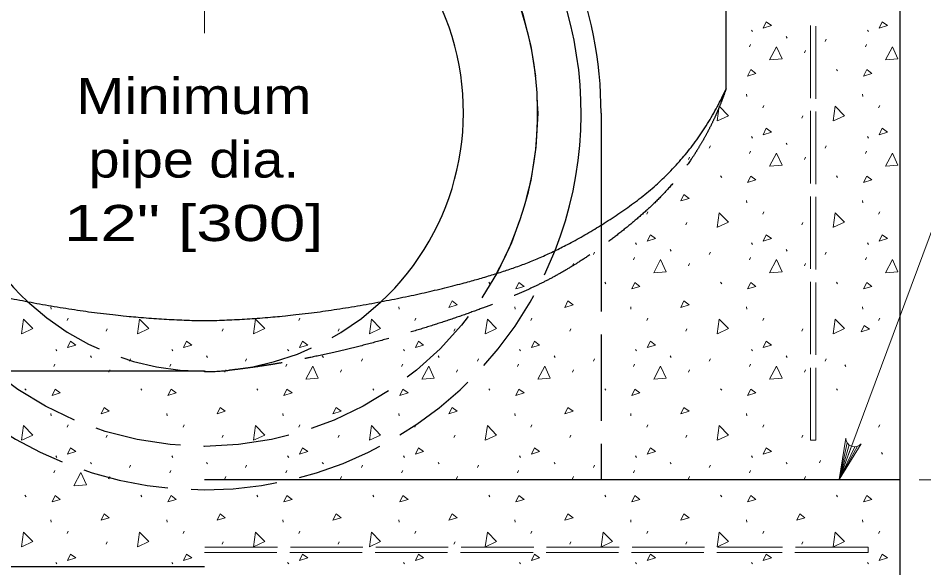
# Model space of a CAD drawing. Extents: x 1083.1 to 1117.1, y 719.4 to 763.4.
# Drawn here: x 1093.643 to 1097.549, y 728.741 to 731.113 of the extents above; entities that cross this region are included whole.
import ezdxf
from ezdxf.enums import TextEntityAlignment as Align

# ---------------------------------------------------------------- set-up
doc = ezdxf.new("R2010")
doc.units = 0
doc.header["$LTSCALE"] = 0.062
doc.linetypes.add('DOT_DASHED', pattern=[7.7, 5, -1.2, 0.3, -1.2])
doc.linetypes.add('LONG_DASHED', pattern=[7.5, 6, -1.5])
doc.layers.add('1', color=7, linetype='Continuous', lineweight=13)

msp = doc.modelspace()

# ---------------------------------------------------------------- linework, layer by layer
at = {"layer": '1', "lineweight": 25}
for p, q in [((1096.69608, 730.80725), (1096.69608, 733.88517)), ((1096.15717, 730.70242), (1096.15717, 730.21942)), ((1094.44633, 729.58892), (1091.19642, 729.58892)), ((1094.03408, 729.12525), (1094.0385, 729.13525)), ((1097.44608, 729.12017), (1094.44633, 729.12017)), ((1094.44633, 728.74525), (1091.19642, 728.74525))]:
    msp.add_line(p, q, dxfattribs=at)
at = {"layer": '1', "linetype": 'DOT_DASHED'}
msp.add_line((1094.44633, 731.04717), (1094.44633, 733.19283), dxfattribs=at)
at = {"layer": '1', "linetype": 'LONG_DASHED'}
for p, q in [((1097.05975, 730.76783), (1097.05975, 731.08033)), ((1097.08258, 730.76508), (1097.08258, 731.07758)), ((1097.05975, 730.39958), (1097.05975, 730.712)), ((1097.08258, 730.39683), (1097.08258, 730.70933)), ((1097.05975, 730.03133), (1097.05975, 730.34375)), ((1097.08258, 730.02858), (1097.08258, 730.341)), ((1097.05975, 729.663), (1097.05975, 729.9755)), ((1097.08258, 729.66025), (1097.08258, 729.97275)), ((1097.05967, 729.29208), (1097.05967, 729.60458)), ((1097.08258, 729.292), (1097.08258, 729.6045)), ((1097.05967, 729.29208), (1097.08258, 729.292)), ((1094.44633, 728.80775), (1094.75875, 728.80775)), ((1094.44908, 728.83058), (1094.7615, 728.83058)), ((1094.81458, 728.80775), (1095.12708, 728.80775)), ((1094.81733, 728.83058), (1095.12983, 728.83058)), ((1095.18292, 728.80775), (1095.49542, 728.80775)), ((1095.18567, 728.83058), (1095.49817, 728.83058)), ((1095.55125, 728.80775), (1095.86375, 728.80775)), ((1095.554, 728.83058), (1095.8665, 728.83058)), ((1095.91958, 728.80775), (1096.23208, 728.80775)), ((1095.92233, 728.83058), (1096.23483, 728.83058)), ((1096.28783, 728.80775), (1096.60033, 728.80775)), ((1096.29058, 728.83058), (1096.60308, 728.83058)), ((1096.65617, 728.80775), (1096.69617, 728.80775)), ((1096.65892, 728.83058), (1096.69617, 728.83058)), ((1096.69617, 728.83058), (1096.94008, 728.83058)), ((1096.69617, 728.80775), (1096.93733, 728.80775)), ((1096.99317, 728.80775), (1097.30842, 728.80775)), ((1096.99592, 728.83058), (1097.30842, 728.83058)), ((1097.30842, 728.83058), (1097.30842, 728.80775))]:
    msp.add_line(p, q, dxfattribs=at)
at = {"layer": '1'}
for p, q in [((1096.80533, 731.06133), (1096.80983, 731.05467)), ((1096.95492, 731.03308), (1096.95933, 731.0265)), ((1097.30533, 731.06133), (1097.30983, 731.05467)), ((1096.797, 730.98817), (1096.80142, 730.99817)), ((1097.12383, 731.01142), (1097.12825, 731.02142)), ((1097.297, 730.98817), (1097.30142, 730.99817)), ((1097.03392, 730.96267), (1097.03833, 730.97267)), ((1097.17267, 730.89167), (1097.17708, 730.885)), ((1096.78483, 730.78517), (1096.786, 730.77517)), ((1097.28483, 730.78517), (1097.286, 730.77517)), ((1096.85408, 730.72625), (1096.8585, 730.73625)), ((1097.35408, 730.72625), (1097.3585, 730.73625)), ((1097.02275, 730.68083), (1097.02725, 730.69083)), ((1096.80533, 730.60208), (1096.80983, 730.59542)), ((1097.30533, 730.60208), (1097.30983, 730.59542)), ((1096.62383, 730.55208), (1096.62825, 730.56208)), ((1096.95492, 730.57375), (1096.95933, 730.56717)), ((1097.12383, 730.55208), (1097.12825, 730.56208)), ((1096.797, 730.52892), (1096.80142, 730.53892)), ((1097.297, 730.52892), (1097.30142, 730.53892)), ((1096.53392, 730.50333), (1096.53833, 730.51333)), ((1097.03392, 730.50333), (1097.03833, 730.51333)), ((1096.67267, 730.43233), (1096.67708, 730.42567)), ((1097.17267, 730.43233), (1097.17708, 730.42567)), ((1096.78483, 730.32583), (1096.786, 730.31583)), ((1097.28483, 730.32583), (1097.286, 730.31583)), ((1096.35408, 730.26692), (1096.3585, 730.27692)), ((1096.85408, 730.26692), (1096.8585, 730.27692)), ((1097.35408, 730.26692), (1097.3585, 730.27692)), ((1096.15792, 730.20992), (1096.15942, 730.22083)), ((1096.52275, 730.22142), (1096.52725, 730.23142)), ((1097.02275, 730.22142), (1097.02725, 730.23142)), ((1096.30533, 730.14275), (1096.30983, 730.13608)), ((1096.80533, 730.14275), (1096.80983, 730.13608)), ((1097.30533, 730.14275), (1097.30983, 730.13608)), ((1095.95925, 730.10817), (1095.95942, 730.10783)), ((1096.12392, 730.09275), (1096.12833, 730.10275)), ((1096.45492, 730.1145), (1096.45933, 730.10783)), ((1096.62383, 730.09275), (1096.62825, 730.10275)), ((1096.95492, 730.1145), (1096.95933, 730.10783)), ((1097.12383, 730.09275), (1097.12825, 730.10275)), ((1096.034, 730.044), (1096.03842, 730.054)), ((1096.297, 730.06958), (1096.30142, 730.07958)), ((1096.53392, 730.044), (1096.53833, 730.054)), ((1096.797, 730.06958), (1096.80142, 730.07958)), ((1097.03392, 730.044), (1097.03833, 730.054)), ((1097.297, 730.06958), (1097.30142, 730.07958)), ((1095.67275, 729.973), (1095.67717, 729.96633)), ((1096.17275, 729.973), (1096.17717, 729.96633)), ((1096.67267, 729.973), (1096.67708, 729.96633)), ((1097.17267, 729.973), (1097.17708, 729.96633)), ((1093.785, 729.8665), (1093.78617, 729.8565)), ((1095.28492, 729.8665), (1095.28608, 729.8565)), ((1095.78492, 729.8665), (1095.78608, 729.8565)), ((1096.28483, 729.8665), (1096.286, 729.8565)), ((1096.78483, 729.8665), (1096.786, 729.8565)), ((1097.28483, 729.8665), (1097.286, 729.8565)), ((1093.85425, 729.80758), (1093.85867, 729.81758)), ((1094.85417, 729.80758), (1094.85858, 729.81758)), ((1095.35417, 729.80758), (1095.35858, 729.81758)), ((1095.85417, 729.80758), (1095.85858, 729.81758)), ((1096.35408, 729.80758), (1096.3585, 729.81758)), ((1096.85408, 729.80758), (1096.8585, 729.81758)), ((1097.35408, 729.80758), (1097.3585, 729.81758)), ((1094.35425, 729.80758), (1094.355, 729.80933)), ((1094.02292, 729.76208), (1094.02742, 729.77208)), ((1094.52283, 729.76208), (1094.52733, 729.77208)), ((1095.02283, 729.76208), (1095.02733, 729.77208)), ((1095.52283, 729.76208), (1095.52733, 729.77208)), ((1096.02283, 729.76208), (1096.02733, 729.77208)), ((1096.52275, 729.76208), (1096.52725, 729.77208)), ((1097.02275, 729.76208), (1097.02725, 729.77208)), ((1093.8055, 729.68333), (1093.81, 729.67667)), ((1094.3055, 729.68333), (1094.31, 729.67667)), ((1094.80542, 729.68333), (1094.80992, 729.67667)), ((1095.30542, 729.68333), (1095.30992, 729.67667)), ((1095.80542, 729.68333), (1095.80992, 729.67667)), ((1096.30533, 729.68333), (1096.30983, 729.67667)), ((1096.80533, 729.68333), (1096.80983, 729.67667)), ((1093.79717, 729.61017), (1093.80158, 729.62017)), ((1093.95508, 729.65508), (1093.9595, 729.64842)), ((1094.124, 729.63333), (1094.12842, 729.64333)), ((1094.29717, 729.61017), (1094.30158, 729.62017)), ((1094.45508, 729.65508), (1094.4595, 729.64842)), ((1094.62392, 729.63333), (1094.62833, 729.64333)), ((1094.79708, 729.61017), (1094.8015, 729.62017)), ((1094.955, 729.65508), (1094.95942, 729.64842)), ((1095.12392, 729.63333), (1095.12833, 729.64333)), ((1095.29708, 729.61017), (1095.3015, 729.62017)), ((1095.455, 729.65508), (1095.45942, 729.64842)), ((1095.62392, 729.63333), (1095.62833, 729.64333)), ((1095.79708, 729.61017), (1095.8015, 729.62017)), ((1095.955, 729.65508), (1095.95942, 729.64842)), ((1096.12392, 729.63333), (1096.12833, 729.64333)), ((1096.297, 729.61017), (1096.30142, 729.62017)), ((1096.45492, 729.65508), (1096.45933, 729.64842)), ((1096.62383, 729.63333), (1096.62825, 729.64333)), ((1096.797, 729.61017), (1096.80142, 729.62017)), ((1096.95492, 729.65508), (1096.95933, 729.64842)), ((1097.12383, 729.63333), (1097.12825, 729.64333)), ((1094.03408, 729.58467), (1094.0385, 729.59467)), ((1094.534, 729.58467), (1094.53842, 729.59467)), ((1095.034, 729.58467), (1095.03842, 729.59467)), ((1095.534, 729.58467), (1095.53842, 729.59467)), ((1096.034, 729.58467), (1096.03842, 729.59467)), ((1096.53392, 729.58467), (1096.53833, 729.59467)), ((1097.03392, 729.58467), (1097.03833, 729.59467)), ((1097.208, 729.6165), (1097.2125, 729.60983)), ((1093.67283, 729.51367), (1093.67725, 729.507)), ((1094.17283, 729.51367), (1094.17725, 729.507)), ((1094.67275, 729.51367), (1094.67717, 729.507)), ((1095.17275, 729.51367), (1095.17717, 729.507)), ((1095.67275, 729.51367), (1095.67717, 729.507)), ((1096.17275, 729.51367), (1096.17717, 729.507)), ((1096.67267, 729.51367), (1096.67708, 729.507)), ((1097.17267, 729.51367), (1097.17708, 729.507)), ((1093.785, 729.40717), (1093.78617, 729.39717)), ((1094.285, 729.40717), (1094.28617, 729.39717)), ((1094.78492, 729.40717), (1094.78608, 729.39717)), ((1095.28492, 729.40717), (1095.28608, 729.39717)), ((1095.78492, 729.40717), (1095.78608, 729.39717)), ((1096.28483, 729.40717), (1096.286, 729.39717)), ((1096.78483, 729.40717), (1096.786, 729.39717)), ((1093.85425, 729.34825), (1093.85867, 729.35825)), ((1094.35425, 729.34825), (1094.35867, 729.35825)), ((1094.85417, 729.34825), (1094.85858, 729.35825)), ((1095.35417, 729.34825), (1095.35858, 729.35825)), ((1095.85417, 729.34825), (1095.85858, 729.35825)), ((1096.35408, 729.34825), (1096.3585, 729.35825)), ((1096.85408, 729.34825), (1096.8585, 729.35825)), ((1097.35408, 729.34825), (1097.3585, 729.35825)), ((1094.02292, 729.30275), (1094.02742, 729.31275)), ((1094.52283, 729.30275), (1094.52733, 729.31275)), ((1095.02283, 729.30275), (1095.02733, 729.31275)), ((1095.52283, 729.30275), (1095.52733, 729.31275)), ((1096.02283, 729.30275), (1096.02733, 729.31275)), ((1096.52275, 729.30275), (1096.52725, 729.31275)), ((1097.02275, 729.30275), (1097.02725, 729.31275)), ((1097.2185, 729.28), (1097.18358, 729.12192)), ((1097.227, 729.271), (1097.18358, 729.12192)), ((1097.23708, 729.2655), (1097.18358, 729.12192)), ((1097.26342, 729.26525), (1097.18358, 729.12192)), ((1097.25158, 729.26308), (1097.18358, 729.12192)), ((1097.36667, 729.23842), (1097.37117, 729.23175)), ((1093.8055, 729.224), (1093.81, 729.21733)), ((1093.95508, 729.19575), (1093.9595, 729.18908)), ((1094.3055, 729.224), (1094.31, 729.21733)), ((1094.45508, 729.19575), (1094.4595, 729.18908)), ((1094.80542, 729.224), (1094.80992, 729.21733)), ((1094.955, 729.19575), (1094.95942, 729.18908)), ((1095.30542, 729.224), (1095.30992, 729.21733)), ((1095.455, 729.19575), (1095.45942, 729.18908)), ((1095.80542, 729.224), (1095.80992, 729.21733)), ((1095.955, 729.19575), (1095.95942, 729.18908)), ((1096.30533, 729.224), (1096.30983, 729.21733)), ((1096.45492, 729.19575), (1096.45933, 729.18908)), ((1096.80533, 729.224), (1096.80983, 729.21733)), ((1096.95492, 729.19575), (1096.95933, 729.18908)), ((1097.09858, 729.19392), (1097.103, 729.20392)), ((1093.79717, 729.15083), (1093.80158, 729.16083)), ((1094.124, 729.174), (1094.12842, 729.184)), ((1094.29717, 729.15083), (1094.30158, 729.16083)), ((1094.62392, 729.174), (1094.62833, 729.184)), ((1094.79708, 729.15083), (1094.8015, 729.16083)), ((1095.12392, 729.174), (1095.12833, 729.184)), ((1095.29708, 729.15083), (1095.3015, 729.16083)), ((1095.62392, 729.174), (1095.62833, 729.184)), ((1095.79708, 729.15083), (1095.8015, 729.16083)), ((1096.12392, 729.174), (1096.12833, 729.184)), ((1096.297, 729.15083), (1096.30142, 729.16083)), ((1096.62383, 729.174), (1096.62825, 729.184)), ((1096.797, 729.15083), (1096.80142, 729.16083)), ((1094.534, 729.12525), (1094.53842, 729.13525)), ((1095.034, 729.12525), (1095.03842, 729.13525)), ((1095.534, 729.12525), (1095.53842, 729.13525)), ((1096.034, 729.12525), (1096.03842, 729.13525)), ((1096.53392, 729.12525), (1096.53833, 729.13525)), ((1097.03392, 729.12525), (1097.03833, 729.13525)), ((1097.52942, 729.12017), (1098.27933, 729.12017)), ((1093.67283, 729.05433), (1093.67725, 729.04767)), ((1094.17283, 729.05433), (1094.17725, 729.04767)), ((1094.67275, 729.05433), (1094.67717, 729.04767)), ((1095.17275, 729.05433), (1095.17717, 729.04767)), ((1095.67275, 729.05433), (1095.67717, 729.04767)), ((1096.17275, 729.05433), (1096.17717, 729.04767)), ((1096.67267, 729.05433), (1096.67708, 729.04767)), ((1097.17267, 729.05433), (1097.17708, 729.04767)), ((1093.785, 728.94783), (1093.78617, 728.93783)), ((1094.285, 728.94783), (1094.28617, 728.93783)), ((1094.78492, 728.94783), (1094.78608, 728.93783)), ((1095.28492, 728.94783), (1095.28608, 728.93783)), ((1095.78492, 728.94783), (1095.78608, 728.93783)), ((1096.28483, 728.94783), (1096.286, 728.93783)), ((1096.78483, 728.94783), (1096.786, 728.93783)), ((1097.28483, 728.94783), (1097.286, 728.93783)), ((1093.85425, 728.88892), (1093.85867, 728.89892)), ((1094.35425, 728.88892), (1094.35867, 728.89892)), ((1094.85417, 728.88892), (1094.85858, 728.89892)), ((1095.35417, 728.88892), (1095.35858, 728.89892)), ((1095.85417, 728.88892), (1095.85858, 728.89892)), ((1096.35408, 728.88892), (1096.3585, 728.89892)), ((1096.85408, 728.88892), (1096.8585, 728.89892)), ((1097.35408, 728.88892), (1097.3585, 728.89892)), ((1094.02292, 728.84342), (1094.02742, 728.85342)), ((1094.52283, 728.84342), (1094.52733, 728.85342)), ((1095.02283, 728.84342), (1095.02733, 728.85342)), ((1095.52283, 728.84342), (1095.52733, 728.85342)), ((1096.02283, 728.84342), (1096.02733, 728.85342)), ((1096.52275, 728.84342), (1096.52725, 728.85342)), ((1097.02275, 728.84342), (1097.02725, 728.85342)), ((1093.8055, 728.76467), (1093.81, 728.758)), ((1094.3055, 728.76467), (1094.31, 728.758)), ((1094.80542, 728.76467), (1094.80992, 728.758)), ((1095.30542, 728.76467), (1095.30992, 728.758)), ((1095.80542, 728.76467), (1095.80992, 728.758)), ((1096.30533, 728.76467), (1096.30983, 728.758)), ((1096.80533, 728.76467), (1096.80983, 728.758)), ((1097.30533, 728.76467), (1097.30983, 728.758))]:
    msp.add_line(p, q, dxfattribs=at)
at = {"layer": '1', "linetype": 'LONG_DASHED', "lineweight": 25}
msp.add_line((1096.15717, 730.21942), (1096.15717, 729.12017), dxfattribs=at)
at = {"layer": '1', "lineweight": 25}
msp.add_lwpolyline([(1097.44608, 733.17933), (1097.44608, 729.87108), (1097.44608, 727.90158)], dxfattribs=at)
at = {"layer": '1'}
for points in [[(1096.85625, 731.06908), (1096.86958, 731.09683), (1096.89183, 731.08017)], [(1097.35625, 731.06908), (1097.36958, 731.09683), (1097.39183, 731.08017)], [(1096.78917, 730.86275), (1096.8025, 730.8905), (1096.82475, 730.87392)], [(1097.28917, 730.86275), (1097.3025, 730.8905), (1097.32475, 730.87392)], [(1096.85625, 730.60975), (1096.86958, 730.6375), (1096.89183, 730.62092)], [(1097.35625, 730.60975), (1097.36958, 730.6375), (1097.39183, 730.62092)], [(1096.78917, 730.40342), (1096.8025, 730.43117), (1096.82475, 730.41458)], [(1097.28917, 730.40342), (1097.3025, 730.43117), (1097.32475, 730.41458)], [(1096.50083, 730.32408), (1096.51417, 730.35183), (1096.53633, 730.33517)], [(1096.35625, 730.15042), (1096.36958, 730.17808), (1096.39183, 730.1615)], [(1096.85625, 730.15042), (1096.86958, 730.17808), (1096.89183, 730.1615)], [(1097.35625, 730.15042), (1097.36958, 730.17808), (1097.39183, 730.1615)], [(1095.78925, 729.94417), (1095.80258, 729.97183), (1095.82483, 729.95525)], [(1096.28917, 729.94417), (1096.3025, 729.97183), (1096.32475, 729.95525)], [(1096.78917, 729.94417), (1096.8025, 729.97183), (1096.82475, 729.95525)], [(1097.28917, 729.94417), (1097.3025, 729.97183), (1097.32475, 729.95525)], [(1095.50092, 729.86475), (1095.51425, 729.8925), (1095.53642, 729.87583)], [(1096.00092, 729.86475), (1096.01425, 729.8925), (1096.03642, 729.87583)], [(1096.50083, 729.86475), (1096.51417, 729.8925), (1096.53633, 729.87583)], [(1097.27875, 729.75917), (1097.29208, 729.78683), (1097.31433, 729.77025)], [(1093.85642, 729.691), (1093.86975, 729.71875), (1093.892, 729.70217)], [(1094.35642, 729.691), (1094.36975, 729.71875), (1094.392, 729.70217)], [(1094.85633, 729.691), (1094.86967, 729.71875), (1094.89192, 729.70217)], [(1095.35633, 729.691), (1095.36967, 729.71875), (1095.39192, 729.70217)], [(1095.85633, 729.691), (1095.86967, 729.71875), (1095.89192, 729.70217)], [(1096.35625, 729.691), (1096.36958, 729.71875), (1096.39183, 729.70217)], [(1096.85625, 729.691), (1096.86958, 729.71875), (1096.89183, 729.70217)], [(1093.78933, 729.48483), (1093.80267, 729.51258), (1093.82492, 729.49592)], [(1094.28933, 729.48483), (1094.30267, 729.51258), (1094.32492, 729.49592)], [(1094.78925, 729.48483), (1094.80258, 729.51258), (1094.82483, 729.49592)], [(1095.28925, 729.48483), (1095.30258, 729.51258), (1095.32483, 729.49592)], [(1095.78925, 729.48483), (1095.80258, 729.51258), (1095.82483, 729.49592)], [(1096.28917, 729.48483), (1096.3025, 729.51258), (1096.32475, 729.49592)], [(1096.78917, 729.48483), (1096.8025, 729.51258), (1096.82475, 729.49592)], [(1094.001, 729.40542), (1094.01433, 729.43317), (1094.0365, 729.41658)], [(1094.50092, 729.40542), (1094.51425, 729.43317), (1094.53642, 729.41658)], [(1095.00092, 729.40542), (1095.01425, 729.43317), (1095.03642, 729.41658)], [(1095.50092, 729.40542), (1095.51425, 729.43317), (1095.53642, 729.41658)], [(1096.00092, 729.40542), (1096.01425, 729.43317), (1096.03642, 729.41658)], [(1096.50083, 729.40542), (1096.51417, 729.43317), (1096.53633, 729.41658)], [(1093.85642, 729.23175), (1093.86975, 729.25942), (1093.892, 729.24283)], [(1094.85633, 729.23175), (1094.86967, 729.25942), (1094.89192, 729.24283)], [(1095.35633, 729.23175), (1095.36967, 729.25942), (1095.39192, 729.24283)], [(1095.85633, 729.23175), (1095.86967, 729.25942), (1095.89192, 729.24283)], [(1096.35625, 729.23175), (1096.36958, 729.25942), (1096.39183, 729.24283)], [(1096.85625, 729.23175), (1096.86958, 729.25942), (1096.89183, 729.24283)], [(1093.78933, 729.0255), (1093.80267, 729.05325), (1093.82492, 729.03658)], [(1094.28933, 729.0255), (1094.30267, 729.05325), (1094.32492, 729.03658)], [(1094.78925, 729.0255), (1094.80258, 729.05325), (1094.82483, 729.03658)], [(1095.28925, 729.0255), (1095.30258, 729.05325), (1095.32483, 729.03658)], [(1095.78925, 729.0255), (1095.80258, 729.05325), (1095.82483, 729.03658)], [(1096.28917, 729.0255), (1096.3025, 729.05325), (1096.32475, 729.03658)], [(1096.78917, 729.0255), (1096.8025, 729.05325), (1096.82475, 729.03658)], [(1097.28917, 729.0255), (1097.3025, 729.05325), (1097.32475, 729.03658)], [(1094.001, 728.94608), (1094.01433, 728.97383), (1094.0365, 728.95725)], [(1094.50092, 728.94608), (1094.51425, 728.97383), (1094.53642, 728.95725)], [(1095.00092, 728.94608), (1095.01425, 728.97383), (1095.03642, 728.95725)], [(1095.50092, 728.94608), (1095.51425, 728.97383), (1095.53642, 728.95725)], [(1096.00092, 728.94608), (1096.01425, 728.97383), (1096.03642, 728.95725)], [(1096.50083, 728.94608), (1096.51417, 728.97383), (1096.53633, 728.95725)], [(1097.00083, 728.94608), (1097.01417, 728.97383), (1097.03633, 728.95725)], [(1093.85642, 728.77242), (1093.86975, 728.80017), (1093.892, 728.7835)], [(1094.35642, 728.77242), (1094.36975, 728.80017), (1094.392, 728.7835)], [(1094.85633, 728.77242), (1094.86967, 728.80017), (1094.89192, 728.7835)], [(1095.35633, 728.77242), (1095.36967, 728.80017), (1095.39192, 728.7835)], [(1095.85633, 728.77242), (1095.86967, 728.80017), (1095.89192, 728.7835)], [(1096.35625, 728.77242), (1096.36958, 728.80017), (1096.39183, 728.7835)], [(1096.85625, 728.77242), (1096.86958, 728.80017), (1096.89183, 728.7835)], [(1097.35625, 728.77242), (1097.36958, 728.80017), (1097.39183, 728.7835)]]:
    msp.add_lwpolyline(points, close=True, dxfattribs=at)
for points in [[(1096.884, 730.93275), (1096.914, 730.98933), (1096.93733, 730.93717), (1096.88517, 730.93275)], [(1097.384, 730.93275), (1097.414, 730.98933), (1097.43733, 730.93717), (1097.38517, 730.93275)], [(1096.65783, 730.66933), (1096.66667, 730.73267), (1096.70642, 730.69175), (1096.65883, 730.66975)], [(1097.15783, 730.66933), (1097.16667, 730.73267), (1097.20642, 730.69175), (1097.15883, 730.66975)], [(1096.884, 730.47342), (1096.914, 730.53), (1096.93733, 730.47783), (1096.88517, 730.47342)], [(1097.384, 730.47342), (1097.414, 730.53), (1097.43733, 730.47783), (1097.38517, 730.47342)], [(1097.18358, 729.12192), (1097.64958, 730.374), (1097.9085, 730.374)], [(1096.65783, 730.20992), (1096.66667, 730.27333), (1096.70642, 730.23233), (1096.65883, 730.21033)], [(1097.15783, 730.20992), (1097.16667, 730.27333), (1097.20642, 730.23233), (1097.15883, 730.21033)], [(1096.384, 730.01408), (1096.414, 730.07067), (1096.43733, 730.0185), (1096.38517, 730.01408)], [(1096.884, 730.01408), (1096.914, 730.07067), (1096.93733, 730.0185), (1096.88517, 730.01408)], [(1097.384, 730.01408), (1097.414, 730.07067), (1097.43733, 730.0185), (1097.38517, 730.01408)], [(1093.658, 729.75058), (1093.66683, 729.814), (1093.70658, 729.773), (1093.659, 729.751)], [(1094.158, 729.75058), (1094.16683, 729.814), (1094.20658, 729.773), (1094.159, 729.751)], [(1094.65792, 729.75058), (1094.66675, 729.814), (1094.7065, 729.773), (1094.65892, 729.751)], [(1095.15792, 729.75058), (1095.16675, 729.814), (1095.2065, 729.773), (1095.15892, 729.751)], [(1095.65792, 729.75058), (1095.66675, 729.814), (1095.7065, 729.773), (1095.65892, 729.751)], [(1096.65783, 729.75058), (1096.66667, 729.814), (1096.70642, 729.773), (1096.65883, 729.751)], [(1097.15783, 729.75058), (1097.16667, 729.814), (1097.20642, 729.773), (1097.15883, 729.751)], [(1094.88408, 729.55475), (1094.91408, 729.61125), (1094.93742, 729.55917), (1094.88525, 729.55475)], [(1095.38408, 729.55475), (1095.41408, 729.61125), (1095.43742, 729.55917), (1095.38525, 729.55475)], [(1095.88408, 729.55475), (1095.91408, 729.61125), (1095.93742, 729.55917), (1095.88525, 729.55475)], [(1096.384, 729.55475), (1096.414, 729.61125), (1096.43733, 729.55917), (1096.38517, 729.55475)], [(1096.884, 729.55475), (1096.914, 729.61125), (1096.93733, 729.55917), (1096.88517, 729.55475)], [(1093.658, 729.29125), (1093.66683, 729.35475), (1093.70658, 729.31367), (1093.659, 729.29167)], [(1094.65792, 729.29125), (1094.66675, 729.35475), (1094.7065, 729.31367), (1094.65892, 729.29167)], [(1095.15792, 729.29125), (1095.16675, 729.35475), (1095.2065, 729.31367), (1095.15892, 729.29167)], [(1095.65792, 729.29125), (1095.66675, 729.35475), (1095.7065, 729.31367), (1095.65892, 729.29167)], [(1096.65783, 729.29125), (1096.66667, 729.35475), (1096.70642, 729.31367), (1096.65883, 729.29167)], [(1097.27858, 729.2755), (1097.18358, 729.12192), (1097.21217, 729.30017)], [(1093.88417, 729.09533), (1093.91417, 729.15192), (1093.9375, 729.09975), (1093.88533, 729.09533)], [(1093.658, 728.83192), (1093.66683, 728.89542), (1093.70658, 728.85433), (1093.659, 728.83233)], [(1094.158, 728.83192), (1094.16683, 728.89542), (1094.20658, 728.85433), (1094.159, 728.83233)], [(1094.65792, 728.83192), (1094.66675, 728.89542), (1094.7065, 728.85433), (1094.65892, 728.83233)], [(1095.15792, 728.83192), (1095.16675, 728.89542), (1095.2065, 728.85433), (1095.15892, 728.83233)], [(1095.65792, 728.83192), (1095.66675, 728.89542), (1095.7065, 728.85433), (1095.65892, 728.83233)], [(1096.15792, 728.83192), (1096.16675, 728.89542), (1096.2065, 728.85433), (1096.15892, 728.83233)], [(1096.65783, 728.83192), (1096.66667, 728.89542), (1096.70642, 728.85433), (1096.65883, 728.83233)], [(1097.15783, 728.83192), (1097.16667, 728.89542), (1097.20642, 728.85433), (1097.15883, 728.83233)]]:
    msp.add_lwpolyline(points, dxfattribs=at)
msp.add_arc((1097.25034, 729.30125), 0.03822, 181.65584, 317.48197, dxfattribs=at)
at = {"layer": '1', "lineweight": 25}
for centre, major_axis, start_param, end_param in [((1094.44629, 730.70244), (-1.62494, 0), 2.7681167, 6.6566612), ((1094.44629, 730.70592), (1.71088, 0), 6.281164, 7.8539816), ((1094.44629, 730.70246), (1.43743, 0), 5.7812107, 9.9267526), ((1094.44633, 730.70595), (-1.1172, 0), 2.3192456, 7.102687)]:
    msp.add_ellipse(centre, major_axis=major_axis, ratio=0.999895, start_param=start_param, end_param=end_param, dxfattribs=at)
at = {"layer": '1', "linetype": 'LONG_DASHED', "lineweight": 25}
msp.add_ellipse((1094.44629, 730.70246), major_axis=(1.43743, 0), ratio=0.999895, dxfattribs=at)
for centre, major_axis, start_param, end_param in [((1094.44628, 730.70248), (-1.62495, 0), 0.3735042, 2.7681435), ((1094.44629, 730.70602), (1.11726, 0), 3.9611587, 5.4608553), ((1094.44304, 730.70477), (1.11726, 0), 4.7152978, 4.8121987)]:
    msp.add_ellipse(centre, major_axis=major_axis, ratio=0.999895, start_param=start_param, end_param=end_param, dxfattribs=at)
at = {"layer": '1', "lineweight": 25}
for points in [[(1092.19642, 730.80742), (1092.33542, 730.50158), (1092.86933, 730.11667), (1093.39125, 729.9415), (1094.11125, 729.81283), (1094.44633, 729.80758)], [(1094.44633, 729.80758), (1094.78133, 729.81283), (1095.50133, 729.9415), (1096.02325, 730.11667), (1096.55717, 730.50158), (1096.69617, 730.80742)]]:
    msp.add_open_spline(points, degree=2, dxfattribs=at)
at = {"layer": '1', "linetype": 'LONG_DASHED', "lineweight": 25}
msp.add_open_spline([(1096.69617, 730.80742), (1096.58758, 730.4895), (1096.09375, 730.05442), (1095.59133, 729.82925), (1094.88733, 729.63108), (1094.55433, 729.59325)], degree=2, dxfattribs=at)

# ---------------------------------------------------------------- texts
at = {"layer": '1'}
for s, width, p in [('Minimum', 1.2, (1094.40079, 730.69892)), ('pipe dia.', 1.15, (1094.40079, 730.42483)), ('12" [300]', 1.35, (1094.40075, 730.15075))]:
    msp.add_text(s, height=0.156, dxfattribs=dict(at, width=width)).set_placement(p, align=Align.CENTER)

doc.saveas('drawing.dxf')
